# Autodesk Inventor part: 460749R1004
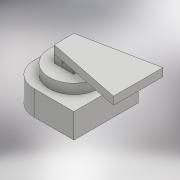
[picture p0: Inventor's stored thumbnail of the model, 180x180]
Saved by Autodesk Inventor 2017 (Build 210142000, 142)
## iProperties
Created: 2016-07
Part Number: 460749R1004
Material: Generic
Document SubType Name: Modeling
Designer: Polytech
Density: 1 g/cm^3
Appearance: Default
Author: Polytech
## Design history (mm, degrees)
sketch "Sketch1"
  geometry: C1 r 23 at (0, 0); 1 further point
  constraints: 1 centre point, 1 coincident
  dimensions: "d0" = 46 diameter of C1
extrude "Extrusion1" new body sketch "Sketch1" distance "d1" = 18; taper "d2" = 0 deg
sketch "Sketch2"
  geometry: L1 (-11.75, -48.75)-(48.75, -48.75); L2 (48.75, -48.75)-(48.75, 48.75); L3 (48.75, 48.75)-(-11.75, 48.75); L4 (-48.75, 11.75)-(-48.75, -11.75); L5 (-48.75, -48.75)-(48.75, 48.75); L6 (48.75, -48.75)-(-48.75, 48.75); A1 r 37 centre (-11.75, 11.75) between (-11.75, 48.75) and (-48.75, 11.75); A2 r 37 centre (-11.75, -11.75) between (-48.75, -11.75) and (-11.75, -48.75); 1 further point
  constraints: 12 end point, 4 point on circle, 4 point on line, 4 tangent, 2 centre point, 2 midpoint, 2 parallel, 1 equal radius, 1 horizontal, 1 perpendicular
  dimensions: "d3" = 97.5 distance of L6.end L2.end; "d4" = 97.5 distance of L2.end L1.end; "d5" = 37 radius of A1
extrude "Extrusion2" join sketch "Sketch2" distance "d6" = 37.5; taper "d7" = 0 deg
sketch "Sketch3"
  geometry: C1 r 37.5 at (0, 0); 1 further point
  constraints: 1 centre point, 1 coincident
  dimensions: "d8" = 75 diameter of C1
extrude "Extrusion3" join sketch "Sketch3" distance "d9" = 15; taper "d10" = 0 deg
sketch "Sketch4"
  geometry: L1 (-15, -15)-(15, -15); L2 (15, -15)-(15, 15); L3 (15, 15)-(-15, 15); L4 (-15, 15)-(-15, -15); L5 (-15, -15)-(15, 15); L6 (15, -15)-(-15, 15); 1 further point
  constraints: 12 end point, 2 midpoint, 2 parallel, 1 horizontal, 1 perpendicular
  dimensions: "d11" = 30 distance of L3.end L2.end; "d12" = 30 distance of L2.end L1.end
extrude "Extrusion4" join sketch "Sketch4" distance "d13" = 12; taper "d14" = 0 deg
sketch "Sketch5"
  geometry: L1 (-15, -6)-(15, -6); L2 (15, -6)-(15, 6); L3 (15, 6)-(-15, 6); L4 (-15, 6)-(-15, -6); L5 (-15, -6)-(15, 6); L6 (15, -6)-(-15, 6); 1 further point
  constraints: 12 end point, 2 midpoint, 2 parallel, 1 horizontal, 1 perpendicular
  dimensions: "d15" = 30 distance of L3.end L2.end; "d16" = 12 distance of L2.end L1.end
extrude "Extrusion5" cut sketch "Sketch5" distance "d17" = 12; taper "d18" = 0 deg
sketch "Sketch6"
  geometry: L1 (52.5, 0)-(-22.5, 0) reference; C1 r 3 at (15, 6); 1 further point
  constraints: 1 centre point, 1 vertical alignment
  dimensions: "d20" = 3 radius of C1; "d21" = 6 distance from line of L1 C1.centre
extrude "Extrusion6" cut sketch "Sketch6" stored distance "d22" = 12; taper "d23" = 0 deg
sketch "Sketch7"
  geometry: L1 (-15, 15)-(-15, -15); L2 (-15, -15)-(97.5, -37.5); L3 (97.5, -37.5)-(97.5, 37.5); L4 (97.5, 37.5)-(-15, 15); 4 further points
  constraints: 8 end point, 2 coincident, 1 horizontal alignment, 1 midpoint, 1 parallel, 1 vertical
  dimensions: "d24" = 75 distance of L2.end L3.end; "d25" = 97.5 distance from line of L3 point (0, 0)
extrude "Extrusion7" join sketch "Sketch7" distance "d26" = 12; taper "d27" = 0 deg
sketch "Sketch8"
  geometry: C1 r 23 at (0, 0); 1 further point
  constraints: 1 centre point, 1 coincident
  dimensions: "d28" = 46 diameter of C1
extrude "Extrusion8" cut sketch "Sketch8" distance "d29" = 24.5; taper "d30" = 0 deg
body "Solid1"
